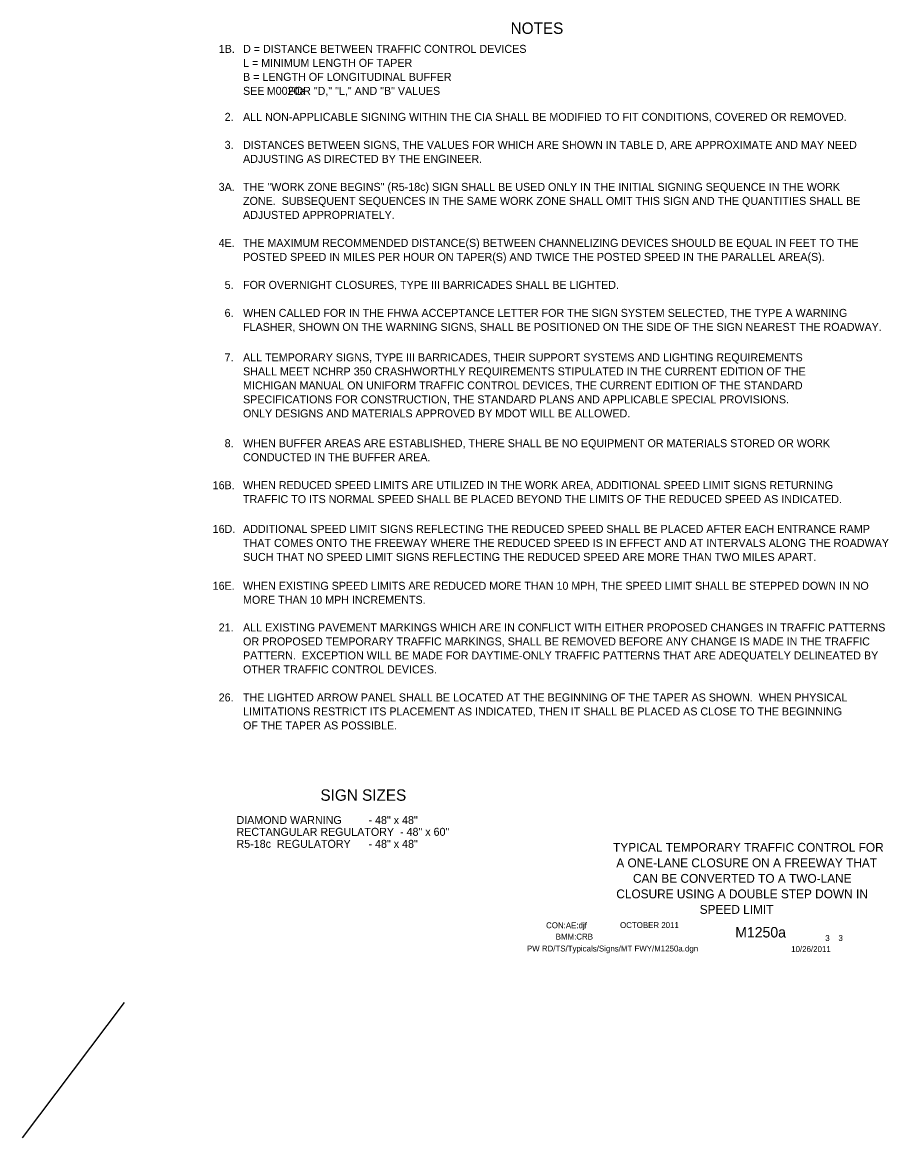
# Model space of a CAD drawing. Extents: x 16576 to 19508, y 5728 to 6974.
# Drawn here: x 18599 to 19508, y 5738 to 6909 of the extents above; entities that cross this region are included whole.
import ezdxf

# ---------------------------------------------------------------- set-up
doc = ezdxf.new("R2010")
doc.units = 0
for name, color, linetype in [('BORDER', 7, 'Continuous'), ('BORDER_SIGNAL_WO', 7, 'Continuous'), ('TYPICAL_TEXT_DIMEN_PR', 7, 'Continuous')]:
    doc.layers.add(name, color=color, linetype=linetype)

msp = doc.modelspace()

# ---------------------------------------------------------------- linework, layer by layer
at = {"layer": 'TYPICAL_TEXT_DIMEN_PR'}
msp.add_line((18705.8, 5880), (18599, 5738.2), dxfattribs=at)

# ---------------------------------------------------------------- texts
at = {"layer": 'BORDER'}
for s, p in [('TYPICAL TEMPORARY TRAFFIC CONTROL FOR', (19219, 6038.4)), ('A ONE-LANE CLOSURE ON A FREEWAY THAT', (19222.4, 6022.1)), ('CAN BE CONVERTED TO A TWO-LANE ', (19239.9, 6005.8)), ('CLOSURE USING A DOUBLE STEP DOWN IN ', (19222.4, 5989.5)), ('SPEED LIMIT', (19309.9, 5973.2))]:
    msp.add_text(s, height=9.3, dxfattribs=at).set_placement(p)
at = {"layer": 'BORDER_SIGNAL_WO'}
for s, height, p in [('CON:AE:djf  ', 6.2, (19148.7, 5958.1)), ('    OCTOBER 2011    ', 6.2, (19217.1, 5958.3)), ('BMM:CRB   ', 6.2, (19158.8, 5946.2)), ('    M1250a   ', 11, (19330.9, 5948.4)), (' 3    3 ', 6.2, (19439.4, 5944.7)), ('PW RD/TS/Typicals/Signs/MT FWY/M1250a.dgn      ', 6.2, (19128.6, 5933.7)), ('10/26/2011    ', 6.2, (19405.9, 5933.1))]:
    msp.add_text(s, height=height, dxfattribs=at).set_placement(p)
at = {"layer": 'TYPICAL_TEXT_DIMEN_PR'}
for s, height, p in [('NOTES', 12, (19111.5, 6897)), ('1B.', 8.4, (18805.2, 6877.1)), ('D = DISTANCE BETWEEN TRAFFIC CONTROL DEVICES', 8.4, (18830.7, 6877.1)), ('L = MINIMUM LENGTH OF TAPER', 8.4, (18830.7, 6862.4)), ('B = LENGTH OF LONGITUDINAL BUFFER', 8.4, (18830.7, 6847.7)), ('SEE        FOR "D," "L," AND "B" VALUES', 8.4, (18830.7, 6833)), ('M0020a', 8.4, (18855.6, 6833)), ('2.', 8.4, (18811.4, 6805.7)), ('ALL NON-APPLICABLE SIGNING WITHIN THE CIA SHALL BE MODIFIED TO FIT CONDITIONS, COVERED OR REMOVED.', 8.4, (18830.7, 6805.7)), ('3.', 8.4, (18811.4, 6776.3)), ('DISTANCES BETWEEN SIGNS, THE VALUES FOR WHICH ARE SHOWN IN TABLE D, ARE APPROXIMATE AND MAY NEED', 8.4, (18830.7, 6776.3)), ('ADJUSTING AS DIRECTED BY THE ENGINEER.', 8.4, (18830.7, 6761.6)), ('3A.', 8.4, (18805.1, 6732.2)), ('THE "WORK ZONE BEGINS" (R5-18c) SIGN SHALL BE USED ONLY IN THE INITIAL SIGNING SEQUENCE IN THE WORK', 8.4, (18830.7, 6732.2)), ('ZONE.  SUBSEQUENT SEQUENCES IN THE SAME WORK ZONE SHALL OMIT THIS SIGN AND THE QUANTITIES SHALL BE', 8.4, (18830.7, 6717.5)), ('ADJUSTED APPROPRIATELY.', 8.4, (18830.7, 6702.8)), ('4E.', 8.4, (18805.1, 6673.4)), ('THE MAXIMUM RECOMMENDED DISTANCE(S) BETWEEN CHANNELIZING DEVICES SHOULD BE EQUAL IN FEET TO THE', 8.4, (18830.7, 6673.4)), ('POSTED SPEED IN MILES PER HOUR ON TAPER(S) AND TWICE THE POSTED SPEED IN THE PARALLEL AREA(S).', 8.4, (18830.7, 6658.7)), ('5.', 8.4, (18811.4, 6629.3)), ('FOR OVERNIGHT CLOSURES, TYPE III BARRICADES SHALL BE LIGHTED.', 8.4, (18830.7, 6629.3)), ('6.', 8.4, (18811.3, 6599.9)), ('WHEN CALLED FOR IN THE FHWA ACCEPTANCE LETTER FOR THE SIGN SYSTEM SELECTED, THE TYPE A WARNING ', 8.4, (18830.7, 6599.9)), ('FLASHER, SHOWN ON THE WARNING SIGNS, SHALL BE POSITIONED ON THE SIDE OF THE SIGN NEAREST THE ROADWAY.', 8.4, (18830.7, 6585.2)), ('7.', 8.4, (18811.3, 6553.2)), ('ALL TEMPORARY SIGNS, TYPE III BARRICADES, THEIR SUPPORT SYSTEMS AND LIGHTING REQUIREMENTS', 8.4, (18830.7, 6553.2)), ('SHALL MEET NCHRP 350 CRASHWORTHLY REQUIREMENTS STIPULATED IN THE CURRENT EDITION OF THE', 8.4, (18830.7, 6538.5)), ('MICHIGAN MANUAL ON UNIFORM TRAFFIC CONTROL DEVICES, THE CURRENT EDITION OF THE STANDARD', 8.4, (18830.7, 6523.8)), ('SPECIFICATIONS FOR CONSTRUCTION, THE STANDARD PLANS AND APPLICABLE SPECIAL PROVISIONS.', 8.4, (18830.7, 6509.1)), ('ONLY DESIGNS AND MATERIALS APPROVED BY MDOT WILL BE ALLOWED.', 8.4, (18830.7, 6494.4)), ('8.', 8.4, (18811.4, 6463.1)), ('WHEN BUFFER AREAS ARE ESTABLISHED, THERE SHALL BE NO EQUIPMENT OR MATERIALS STORED OR WORK     ', 8.4, (18830.7, 6463.1)), ('CONDUCTED IN THE BUFFER AREA.', 8.4, (18830.7, 6448.4)), ('16B.', 8.4, (18798.8, 6419)), ('WHEN REDUCED SPEED LIMITS ARE UTILIZED IN THE WORK AREA, ADDITIONAL SPEED LIMIT SIGNS RETURNING', 8.4, (18830.7, 6419.1)), ('TRAFFIC TO ITS NORMAL SPEED SHALL BE PLACED BEYOND THE LIMITS OF THE REDUCED SPEED AS INDICATED.', 8.4, (18830.7, 6404.4)), ('16D.', 8.4, (18798.8, 6373.1)), ('ADDITIONAL SPEED LIMIT SIGNS REFLECTING THE REDUCED SPEED SHALL BE PLACED AFTER EACH ENTRANCE RAMP', 8.4, (18830.7, 6373.1)), ('THAT COMES ONTO THE FREEWAY WHERE THE REDUCED SPEED IS IN EFFECT AND AT INTERVALS ALONG THE ROADWAY', 8.4, (18830.7, 6358.4)), ('SUCH THAT NO SPEED LIMIT SIGNS REFLECTING THE REDUCED SPEED ARE MORE THAN TWO MILES APART.', 8.4, (18830.7, 6343.7)), ('16E.', 8.4, (18798.8, 6313.4)), ('WHEN EXISTING SPEED LIMITS ARE REDUCED MORE THAN 10 MPH, THE SPEED LIMIT SHALL BE STEPPED DOWN IN NO', 8.4, (18830.7, 6313.4)), ('MORE THAN 10 MPH INCREMENTS.', 8.4, (18830.7, 6298.7)), ('21.', 8.4, (18805.1, 6269.7)), ('ALL EXISTING PAVEMENT MARKINGS WHICH ARE IN CONFLICT WITH EITHER PROPOSED CHANGES IN TRAFFIC PATTERNS', 8.4, (18830.7, 6269.7)), ('OR PROPOSED TEMPORARY TRAFFIC MARKINGS, SHALL BE REMOVED BEFORE ANY CHANGE IS MADE IN THE TRAFFIC', 8.4, (18830.7, 6255)), ('PATTERN.  EXCEPTION WILL BE MADE FOR DAYTIME-ONLY TRAFFIC PATTERNS THAT ARE ADEQUATELY DELINEATED BY', 8.4, (18830.7, 6240.3)), ('OTHER TRAFFIC CONTROL DEVICES.', 8.4, (18830.7, 6225.6)), ('26.', 8.4, (18805.1, 6196.2)), ('THE LIGHTED ARROW PANEL SHALL BE LOCATED AT THE BEGINNING OF THE TAPER AS SHOWN.  WHEN PHYSICAL', 8.4, (18830.7, 6196.2)), ('LIMITATIONS RESTRICT ITS PLACEMENT AS INDICATED, THEN IT SHALL BE PLACED AS CLOSE TO THE BEGINNING', 8.4, (18830.7, 6181.5)), ('OF THE TAPER AS POSSIBLE.', 8.4, (18830.7, 6166.8)), ('SIGN SIZES', 12, (18911.9, 6091.9)), ('DIAMOND WARNING         - 48" x 48"', 8.4, (18823.8, 6067.5)), ('RECTANGULAR REGULATORY  - 48" x 60"', 8.4, (18823.8, 6055.1)), ('R5-18c  REGULATORY      - 48" x 48"', 8.4, (18823.8, 6042.5))]:
    msp.add_text(s, height=height, dxfattribs=at).set_placement(p)

doc.saveas('drawing.dxf')
